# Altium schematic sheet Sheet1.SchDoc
size A4
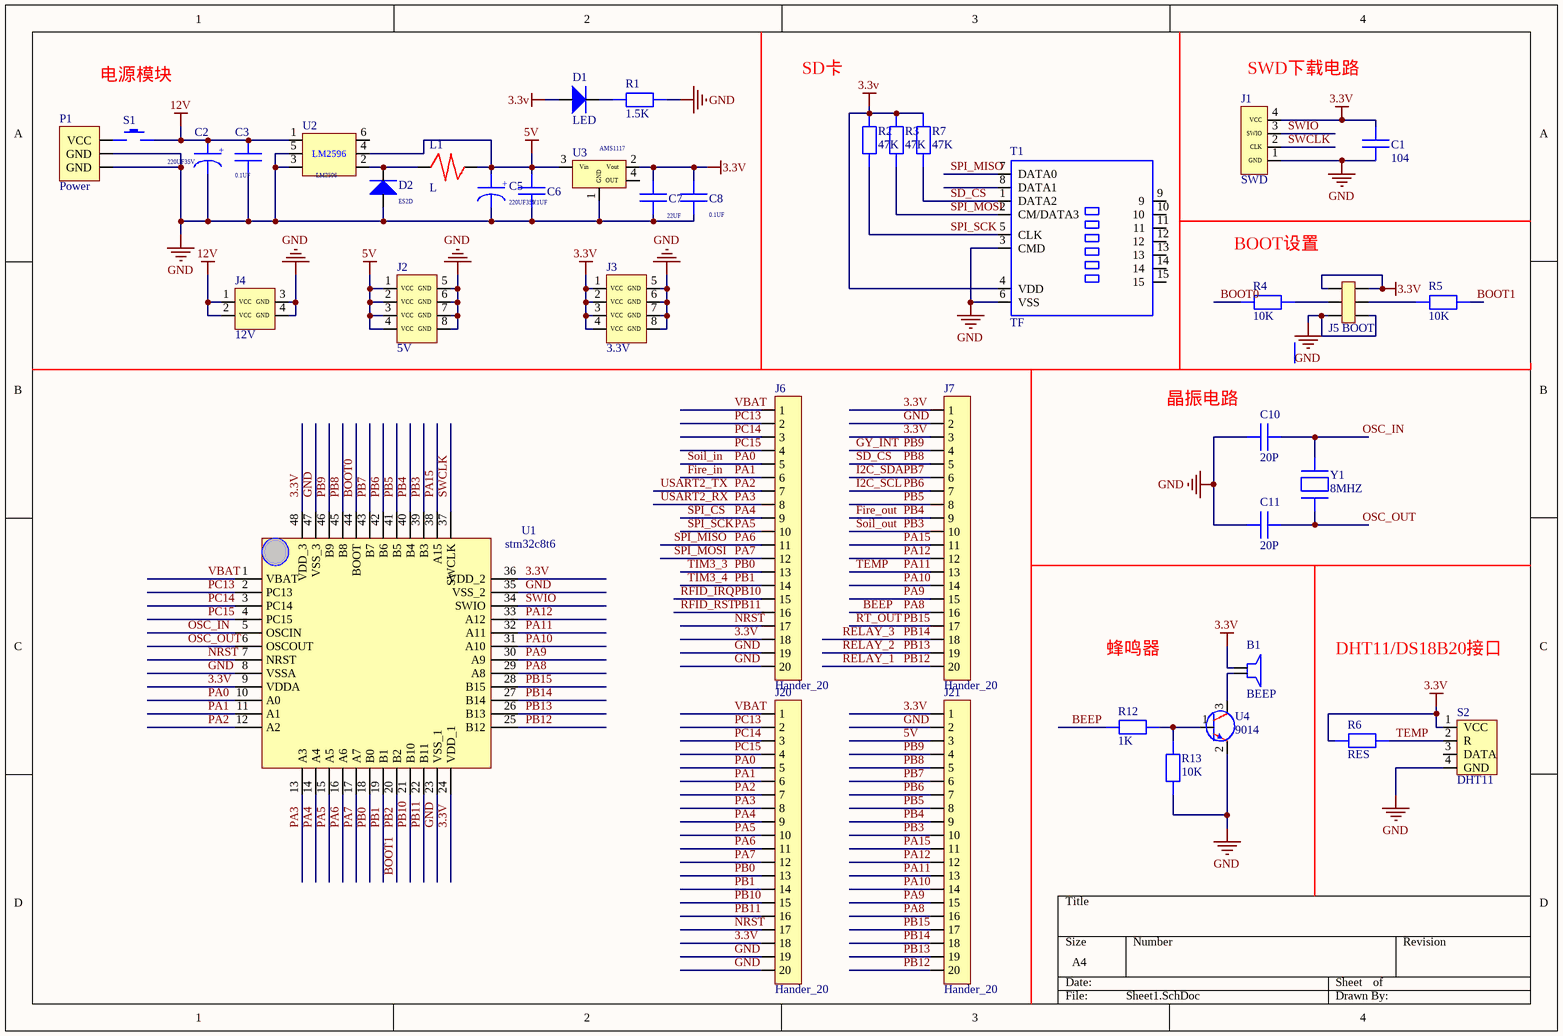
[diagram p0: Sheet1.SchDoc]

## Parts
B1  BEEP  [BEEP-9.5X5.5]
C1  104  [CAP_0603_FIRE]
C2  220UF35V  [CAP+_47UF_FIRE]
C3  0.1UF  [CAP_0603_FIRE]
C5  220UF35V  [CAP+_47UF_FIRE]
C6  0.1UF  [CAP_0603_FIRE]
C7  22UF  [CAP_0603_FIRE]
C8  0.1UF  [CAP_0603_FIRE]
C10  20P  [CAP_0603_FIRE]
C11  20P  [CAP_0603_FIRE]
D1  LED  [LED_Z]
D2  ES2D  [LED_Z]
J1  SWD  [SWD]
J2  5V  [5V]
J3  3.3V  [3.3V]
J4  12V  [12V]
J5  BOOT  [BOOT]
J6  Hander_20  [Hander_20]
J7  Hander_20  [Hander_20]
J20  Hander_20  [Hander_20]
J21  Hander_20  [Hander_20]
L1  L  [L]
P1  Power  [POWER]
R1  1.5K  [R_0603]
R2  47K  [R_0603]
R3  47K  [R_0603]
R4  10K  [R_0603]
R5  10K  [R_0603]
R6  RES  [R_0603]
R7  47K  [R_0603]
R12  1K  [R_0603]
R13  10K  [R_0603]
S1  (no value)  [SWITCH]
S2  DHT11  [DHT11]
T1  TF  [TF_CARD]
U1  stm32c8t6  [LQFP48_N]
U2  LM2596  [LM2596]
U3  AMS1117  [AMS-1117-3.3]
U4  9014  [SOT-23]
Y1  8MHZ  [XTAL_socket]

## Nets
3.3V: B1.1 C1.2 C7.2 C8.2 D1.1 J1.4(VCC) J3.1(VCC) J3.2(VCC) J3.3(VCC) J3.4(VCC) J5.1 J5.6 J6.18 J7.1 J7.3 J20.18 J21.1 R2.2 R3.2 R6.1 R7.2 S2.1(VCC) T1.4(VDD) U1.9(VDDA) U1.24(VDD_1) U1.36(VDD_2) U1.48(VDD_3) U3.2(Vout)
5V: C5.1 C6.1 J2.1(VCC) J2.2(VCC) J2.3(VCC) J2.4(VCC) J21.3 L1.2 U2.4 U3.3(Vin)
12V: C2.1 C3.2 J4.1(VCC) J4.2(VCC) S1.2(VCC) U2.1
GND: C1.1 C2.2 C3.1 C5.2 C6.2 C7.1 C8.1 C10.1 C11.1 D2.1 J1.1(GND) J2.5(GND) J2.6(GND) J2.7(GND) J2.8(GND) J3.5(GND) J3.6(GND) J3.7(GND) J3.8(GND) J4.3(GND) J4.4(GND) J5.3 J5.4 J6.19 J6.20 J7.2 J20.19 J20.20 J21.2 P1.1(GND) P1.2(GND) R1.2 R13.1 S2.4(GND) T1.3(CMD) T1.6(VSS) U1.8(VSSA) U1.23(VSS_1) U1.35(VSS_2) U1.47(VSS_3) U2.3 U2.5 U3.1(GND) U4.2
BEEP: J7.16 J21.16 R12.1 U1.29(A8)  [also labelled PA8]
BOOT0: R4.1 U1.44(BOOT)
BOOT1: R5.2 U1.20(B2)  [also labelled PB2]
Fire_in: J6.6 J20.6 U1.11(A1)  [also labelled PA1]
Fire_out: J7.9 J21.9 U1.40(B4)  [also labelled PB4]
GY_INT: J7.4 J21.4 U1.46(B9)  [also labelled PB9]
I2C_SCL: J7.7 J21.7 U1.42(B6)  [also labelled PB6]
I2C_SDA: J7.6 J21.6 U1.43(B7)  [also labelled PB7]
NRST: J6.17 J20.17 U1.7(NRST)
OSC_IN: C10.2 U1.5(OSCIN) Y1.2
OSC_OUT: C11.2 U1.6(OSCOUT) Y1.1
PA0: J6.5 J20.5 U1.10(A0)  [also labelled Soil_in]
PA2: J6.7 J20.7 U1.12(A2)  [also labelled USART2_TX]
PA3: J6.8 J20.8 U1.13(A3)  [also labelled USART2_RX]
PA4: J6.9 J20.9 U1.14(A4)  [also labelled SPI_CS]
PA5: J6.10 J20.10 R2.1 T1.5(CLK) U1.15(A5)  [also labelled SPI_SCK]
PA6: J6.11 J20.11 T1.7(DATA0) U1.16(A6)  [also labelled SPI_MISO]
PA7: J6.12 J20.12 R3.1 T1.2(CM/DATA3) U1.17(A7)  [also labelled SPI_MOSI]
PA9: J7.15 J21.15 U1.30(A9)
PA10: J7.14 J21.14 U1.31(A10)
PA11: J7.13 J21.13 R6.2 S2.2(R) U1.32(A11)  [also labelled TEMP]
PA12: J7.12 J21.12 U1.33(A12)
PA15: J7.11 J21.11 U1.38(A15)
PB0: J6.13 J20.13 U1.18(B0)  [also labelled TIM3_3]
PB1: J6.14 J20.14 U1.19(B1)  [also labelled TIM3_4]
PB3: J7.10 J21.10 U1.39(B3)  [also labelled Soil_out]
PB5: J7.8 J21.8 U1.41(B5)
PB8: J7.5 J21.5 R7.1 T1.1(DATA2) U1.45(B8)  [also labelled SD_CS]
PB10: J6.15 J20.15 U1.21(B10)  [also labelled RFID_IRQ]
PB11: J6.16 J20.16 U1.22(B11)  [also labelled RFID_RST]
PB12: J7.20 J21.20 U1.25(B12)  [also labelled RELAY_1]
PB13: J7.19 J21.19 U1.26(B13)  [also labelled RELAY_2]
PB14: J7.18 J21.18 U1.27(B14)  [also labelled RELAY_3]
PB15: J7.17 J21.17 U1.28(B15)  [also labelled RT_OUT]
PC13: J6.2 J20.2 U1.2(PC13)
PC14: J6.3 J20.3 U1.3(PC14)
PC15: J6.4 J20.4 U1.4(PC15)
SWCLK: J1.2(CLK) U1.37(SWCLK)
SWIO: J1.3(SWIO) U1.34(SWIO)
VBAT: J6.1 J20.1 U1.1(VBAT)
NetB1_2: B1.2 U4.3
NetD1_2: D1.2 R1.1
NetD2_2: D2.2 L1.1 U2.2
NetJ5_2: J5.2 R4.2
NetJ5_5: J5.5 R5.1
NetP1_3: P1.3(VCC) S1.1(VCC)
NetR12_2: R12.2 R13.2 U4.1

Not connected (* = marked no-connect by the designer): S2 3(DATA); T1 8(DATA1) 9 10 11 12 13 14 15; U2 6; U3 4(OUT)

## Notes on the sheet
- 电源模块
- SD卡
- (near J1) SWD下载电路
- BOOT设置
- 晶振电路
- 蜂鸣器
- DHT11/DS18B20接口

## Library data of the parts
C1 C3 C6-C8 C10 C11 = Capacitance
C2 C5 = Capactiance+
D2 = LED
R1-R5 R7 R12 R13 = RES
S1 = Switch
Y1 = XTAL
